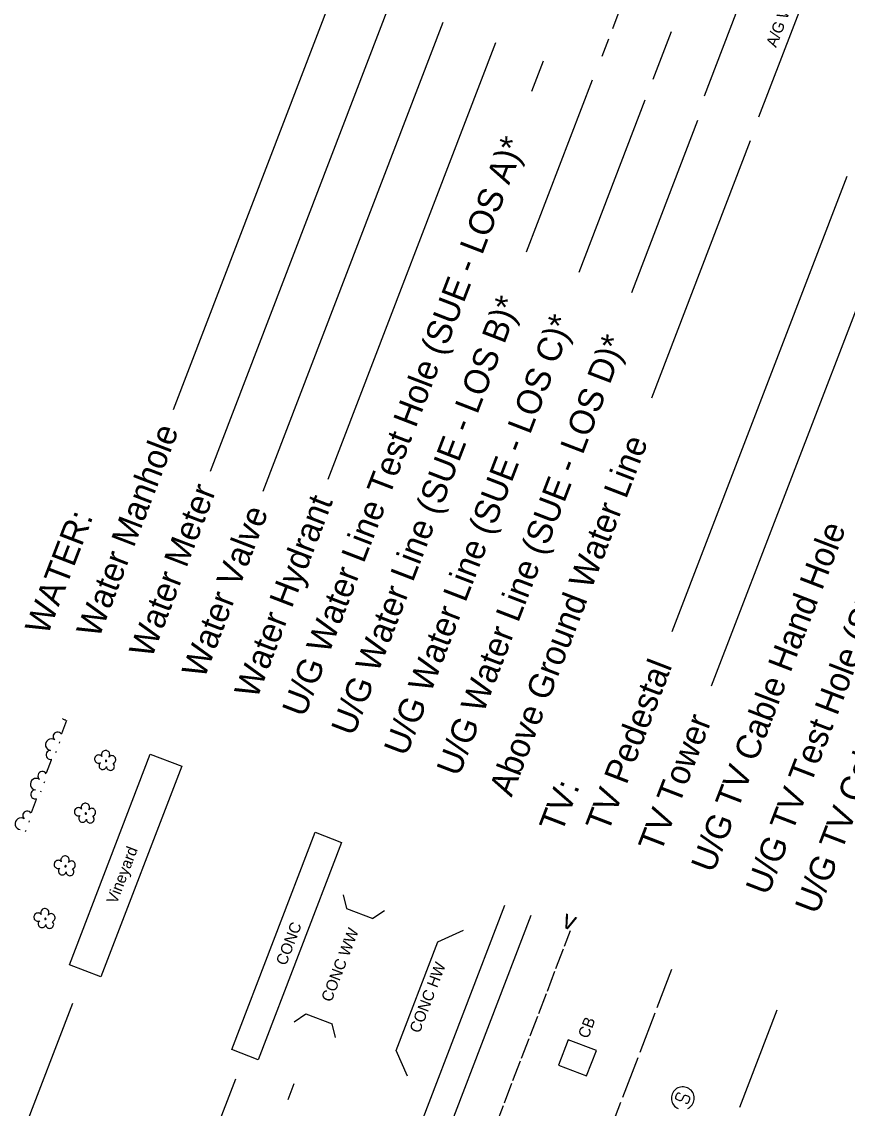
# Model space of a CAD drawing. Extents: x 1015221 to 1064345, y 619216 to 647967.
# Drawn here: x 1047324 to 1049619, y 632823 to 635845 of the extents above; entities that cross this region are included whole.
import ezdxf

# ---------------------------------------------------------------- set-up
doc = ezdxf.new("R2010")
doc.units = 0
doc.layers.add('Default', color=7, linetype='Continuous')

msp = doc.modelspace()

# ---------------------------------------------------------------- linework, layer by layer
at = {"layer": 'Default'}
for p, q in [((1049373.4, 635580.1), (1049609.8, 636195.4)), ((1048201.7, 635954.5), (1047744.7, 634765.2)), ((1049222.1, 635638.2), (1049332.7, 635926.1)), ((1048348.2, 635898.3), (1047847.2, 634594.3)), ((1048967.1, 635825.8), (1048985.4, 635873.4)), ((1048494.7, 635842), (1047993.7, 634538)), ((1049079.3, 635685), (1049130.3, 635817.8)), ((1048641.1, 635785.7), (1048174.6, 634571.4)), ((1048937.6, 635748.9), (1048955.9, 635796.5)), ((1048773.6, 635734.8), (1048741.1, 635650.2)), ((1048910.2, 635682.3), (1048726.2, 635203.5)), ((1049056.7, 635626), (1048872.7, 635147.2)), ((1049203.1, 635569.8), (1049019.2, 635090.9)), ((1049349.6, 635513.5), (1049074.7, 634797.8)), ((1049617.9, 635414.4), (1049131.3, 634148)), ((1049764.4, 635358.2), (1049241.4, 633997)), ((1047434.9, 633865.8), (1047448.9, 633902.4)), ((1047428.5, 633838.4), (1047429.9, 633842)), ((1047418.7, 633812.7), (1047420.1, 633816.4)), ((1047392.6, 633755.9), (1047406.7, 633792.5)), ((1047386.3, 633728.5), (1047387.7, 633732.2)), ((1047376.5, 633702.9), (1047377.9, 633706.5)), ((1047350.4, 633646), (1047364.5, 633682.7)), ((1047344.1, 633618.6), (1047345.5, 633622.3)), ((1047334.3, 633593), (1047335.7, 633596.7)), ((1048217.1, 633417.1), (1048226.5, 633379)), ((1048435, 632784.1), (1048667.1, 633388.3)), ((1048226.5, 633379), (1048299.7, 633350.9)), ((1048332.3, 633372.8), (1048299.7, 633350.9)), ((1048508.2, 632756), (1048740.4, 633360.2)), ((1048480.9, 633286.5), (1048552.6, 633318.4)), ((1048833.3, 633274), (1048850.2, 633318)), ((1048364.8, 632984.4), (1048480.9, 633286.5)), ((1048809.4, 633211.8), (1048830.5, 633266.7)), ((1049090.9, 633103.6), (1049131.7, 633209.8)), ((1048785.5, 633149.5), (1048806.6, 633204.5)), ((1048761.6, 633087.3), (1048782.7, 633142.2)), ((1047465.1, 633114.8), (1046888.4, 631613.8)), ((1048081.4, 633064.1), (1048113.9, 633086)), ((1048113.9, 633086), (1048187.2, 633057.9)), ((1049043.1, 632979.1), (1049085.3, 633089)), ((1049320.7, 632826.5), (1049424.7, 633097.3)), ((1048196.6, 633019.8), (1048187.2, 633057.9)), ((1048737.7, 633025), (1048758.8, 633080)), ((1048713.7, 632962.8), (1048734.9, 633017.7)), ((1048396.7, 632912.7), (1048364.8, 632984.4)), ((1048689.8, 632900.5), (1048710.9, 632955.4)), ((1048995.3, 632854.6), (1049037.5, 632964.5)), ((1047918.1, 632904.5), (1047701.5, 632340.8)), ((1048064.6, 632848.2), (1048081.4, 632892.1)), ((1048665.9, 632838.3), (1048687, 632893.2)), ((1049142.5, 632854.9), (1049145.5, 632862.8)), ((1049153.5, 632844.6), (1049145.7, 632847.6)), ((1049152.6, 632865.7), (1049155.2, 632864.7)), ((1049163.6, 632855.8), (1049160.5, 632848)), ((1049178.6, 632855.8), (1049170.5, 632858.9)), ((1049178.6, 632841), (1049181.6, 632848.9)), ((1048642, 632776), (1048663.1, 632830.9)), ((1048947.4, 632730.1), (1048989.6, 632840)), ((1049169, 632838.7), (1049171.6, 632837.7))]:
    msp.add_line(p, q, dxfattribs=at)
for points in [[(1047577.6, 633781.8), (1047581.9, 633785.2), (1047583.5, 633787.1), (1047584.7, 633789.2), (1047585.2, 633791.5), (1047585.1, 633793.6), (1047584.7, 633795.9), (1047584, 633798.3), (1047582.6, 633800.1), (1047581, 633801.5), (1047579.1, 633803.1), (1047576.8, 633803.5), (1047574.4, 633804), (1047571.7, 633803.4), (1047569.8, 633802.9), (1047568, 633801.5), (1047566, 633799.7), (1047567.2, 633801.7), (1047568.2, 633804.3), (1047568.2, 633806.4), (1047567.9, 633809), (1047567.6, 633811.3), (1047566.3, 633813.5), (1047564.5, 633815.4), (1047562.5, 633816.6), (1047560.4, 633817.8), (1047558.1, 633818.3), (1047555.6, 633818.4), (1047553.2, 633817.6), (1047550.7, 633816.5), (1047548.8, 633815.1), (1047547.3, 633813.2), (1047546.1, 633811.1), (1047545.2, 633808.9), (1047545.1, 633806.5), (1047545.5, 633804.2), (1047546.3, 633801.8)], [(1047456.1, 633222.5), (1047681.2, 633808.4), (1047769.1, 633774.6), (1047543.9, 633188.7), (1047456.1, 633222.5)], [(1047546.3, 633801.8), (1047544.5, 633803.8), (1047542.4, 633805), (1047540.1, 633805.4), (1047537.8, 633805.9), (1047535.5, 633805.5), (1047533.2, 633805.1), (1047531.1, 633803.9), (1047529.3, 633802.5), (1047527.6, 633800.2), (1047526.9, 633798.3), (1047526.4, 633796), (1047526.3, 633793.5), (1047526.7, 633791.3), (1047527.4, 633788.9), (1047529.2, 633786.9), (1047530.7, 633785.5), (1047532.8, 633784.3), (1047535, 633783.4), (1047537.3, 633783), (1047539.6, 633783.4), (1047542.4, 633784), (1047540.6, 633782.6), (1047539.3, 633780.5), (1047538.5, 633778.3), (1047538.5, 633776.2), (1047538.6, 633774.1), (1047539.3, 633771.7), (1047540.2, 633769.7), (1047541.6, 633767.9), (1047543.3, 633766.8), (1047545.7, 633765.5), (1047547.7, 633765.1), (1047549.8, 633765.1), (1047552.2, 633765.9), (1047554.1, 633766.4), (1047555.9, 633767.9), (1047557.9, 633769.6), (1047558.9, 633771.3), (1047559.8, 633773.5), (1047559.8, 633771.4), (1047560.6, 633769), (1047561.6, 633767.3), (1047563.5, 633765.8), (1047565.4, 633764.2), (1047567.3, 633763.5), (1047569.6, 633763), (1047571.9, 633763.4), (1047574.1, 633763.8), (1047576.1, 633764.7), (1047577.9, 633766.1), (1047579.4, 633767.7), (1047580.2, 633769.9), (1047581.1, 633772.1), (1047581.4, 633774), (1047580.6, 633776.4), (1047580.2, 633778.7), (1047577.6, 633781.8)], [(1047556.7, 633790.7), (1047556.3, 633789.6), (1047556.4, 633788.7), (1047556.4, 633787.8), (1047557.5, 633787.4), (1047558.3, 633787.1), (1047559.3, 633787.6), (1047559.7, 633788.7), (1047560, 633789.4), (1047559.5, 633790.4), (1047558.6, 633791.2), (1047557.7, 633791.1), (1047556.7, 633790.7)], [(1047521.4, 633635.3), (1047525.6, 633638.7), (1047527.2, 633640.6), (1047528.4, 633642.7), (1047528.9, 633645), (1047528.9, 633647.1), (1047528.5, 633649.4), (1047527.7, 633651.8), (1047526.3, 633653.6), (1047524.7, 633655), (1047522.8, 633656.6), (1047520.5, 633657.1), (1047518.1, 633657.5), (1047515.4, 633656.9), (1047513.5, 633656.4), (1047511.7, 633655), (1047509.8, 633653.2), (1047511, 633655.3), (1047512, 633657.8), (1047511.9, 633659.9), (1047511.7, 633662.6), (1047511.3, 633664.8), (1047510, 633667), (1047508.2, 633668.9), (1047506.2, 633670.1), (1047504.1, 633671.3), (1047501.8, 633671.8), (1047499.3, 633671.9), (1047496.9, 633671.2), (1047494.4, 633670), (1047492.6, 633668.6), (1047491, 633666.7), (1047489.8, 633664.7), (1047488.9, 633662.5), (1047488.8, 633660), (1047489.2, 633657.7), (1047490, 633655.3)], [(1047490, 633655.3), (1047488.2, 633657.3), (1047486.2, 633658.5), (1047483.8, 633659), (1047481.5, 633659.4), (1047479.2, 633659), (1047477, 633658.7), (1047474.8, 633657.4), (1047473, 633656), (1047471.3, 633653.7), (1047470.6, 633651.9), (1047470.1, 633649.5), (1047470, 633647), (1047470.4, 633644.8), (1047471.1, 633642.4), (1047472.9, 633640.5), (1047474.5, 633639), (1047476.5, 633637.8), (1047478.7, 633637), (1047481.1, 633636.5), (1047483.3, 633636.9), (1047486.1, 633637.5), (1047484.3, 633636.1), (1047483.1, 633634), (1047482.2, 633631.8), (1047482.2, 633629.7), (1047482.3, 633627.6), (1047483, 633625.2), (1047483.9, 633623.2), (1047485.3, 633621.4), (1047487, 633620.3), (1047489.5, 633619), (1047491.4, 633618.6), (1047493.5, 633618.7), (1047495.9, 633619.4), (1047497.8, 633620), (1047499.6, 633621.4), (1047501.6, 633623.1), (1047502.6, 633624.8), (1047503.5, 633627), (1047503.5, 633624.9), (1047504.3, 633622.5), (1047505.3, 633620.9), (1047507.2, 633619.3), (1047509.1, 633617.7), (1047511, 633617), (1047513.3, 633616.5), (1047515.6, 633616.9), (1047517.8, 633617.3), (1047519.9, 633618.2), (1047521.7, 633619.6), (1047523.1, 633621.2), (1047523.9, 633623.4), (1047524.8, 633625.6), (1047525.1, 633627.5), (1047524.4, 633629.9), (1047524, 633632.2), (1047521.4, 633635.3)], [(1047500.4, 633644.2), (1047500, 633643.1), (1047500.1, 633642.2), (1047500.2, 633641.3), (1047501.3, 633640.9), (1047502, 633640.6), (1047503, 633641.1), (1047503.4, 633642.2), (1047503.7, 633642.9), (1047503.3, 633643.9), (1047502.3, 633644.7), (1047501.4, 633644.6), (1047500.4, 633644.2)], [(1047907.7, 632986.7), (1048139.8, 633590.9), (1048213.1, 633562.8), (1047980.9, 632958.5), (1047907.7, 632986.7)], [(1047433.7, 633508.8), (1047431.9, 633510.8), (1047429.9, 633512), (1047427.5, 633512.5), (1047425.2, 633513), (1047422.9, 633512.6), (1047420.7, 633512.2), (1047418.5, 633510.9), (1047416.7, 633509.5), (1047415, 633507.2), (1047414.3, 633505.4), (1047413.8, 633503), (1047413.7, 633500.6), (1047414.1, 633498.3), (1047414.9, 633495.9), (1047416.6, 633494), (1047418.2, 633492.5), (1047420.2, 633491.3), (1047422.4, 633490.5), (1047424.8, 633490), (1047427, 633490.4), (1047429.8, 633491), (1047428, 633489.6), (1047426.8, 633487.6), (1047425.9, 633485.4), (1047426, 633483.2), (1047426, 633481.1), (1047426.8, 633478.7), (1047427.7, 633476.7), (1047429.1, 633474.9), (1047430.8, 633473.8), (1047433.2, 633472.5), (1047435.2, 633472.1), (1047437.3, 633472.2), (1047439.7, 633472.9), (1047441.5, 633473.5), (1047443.3, 633474.9), (1047445.3, 633476.7), (1047446.4, 633478.4), (1047447.2, 633480.5), (1047447.2, 633478.4), (1047448, 633476), (1047449, 633474.4), (1047451, 633472.8), (1047452.9, 633471.2), (1047454.7, 633470.5), (1047457, 633470), (1047459.3, 633470.4), (1047461.5, 633470.8), (1047463.6, 633471.7), (1047465.4, 633473.1), (1047466.8, 633474.7), (1047467.7, 633476.9), (1047468.5, 633479.1), (1047468.8, 633481.1), (1047468.1, 633483.5), (1047467.7, 633485.7), (1047465.1, 633488.8)], [(1047465.1, 633488.8), (1047469.3, 633492.2), (1047470.9, 633494.1), (1047472.1, 633496.2), (1047472.6, 633498.5), (1047472.6, 633500.6), (1047472.2, 633502.9), (1047471.4, 633505.3), (1047470, 633507.1), (1047468.5, 633508.5), (1047466.5, 633510.1), (1047464.2, 633510.6), (1047461.9, 633511.1), (1047459.1, 633510.4), (1047457.2, 633509.9), (1047455.4, 633508.5), (1047453.5, 633506.7), (1047454.7, 633508.8), (1047455.7, 633511.3), (1047455.6, 633513.4), (1047455.4, 633516.1), (1047455, 633518.3), (1047453.7, 633520.5), (1047452, 633522.4), (1047449.9, 633523.6), (1047447.8, 633524.9), (1047445.5, 633525.3), (1047443, 633525.4), (1047440.6, 633524.7), (1047438.1, 633523.6), (1047436.3, 633522.1), (1047434.7, 633520.2), (1047433.5, 633518.2), (1047432.7, 633516), (1047432.5, 633513.5), (1047432.9, 633511.2), (1047433.7, 633508.8)], [(1047444.1, 633497.7), (1047443.7, 633496.6), (1047443.8, 633495.7), (1047443.9, 633494.9), (1047445, 633494.4), (1047445.7, 633494.2), (1047446.7, 633494.6), (1047447.1, 633495.7), (1047447.4, 633496.4), (1047447, 633497.4), (1047446, 633498.2), (1047445.1, 633498.2), (1047444.1, 633497.7)], [(1047377.4, 633362.4), (1047375.6, 633364.3), (1047373.6, 633365.5), (1047371.3, 633366), (1047368.9, 633366.5), (1047366.7, 633366.1), (1047364.4, 633365.7), (1047362.2, 633364.4), (1047360.4, 633363), (1047358.7, 633360.7), (1047358, 633358.9), (1047357.5, 633356.6), (1047357.4, 633354.1), (1047357.8, 633351.8), (1047358.6, 633349.4), (1047360.4, 633347.5), (1047361.9, 633346.1), (1047364, 633344.8), (1047366.2, 633344), (1047368.5, 633343.5), (1047370.8, 633343.9), (1047373.5, 633344.5), (1047371.7, 633343.1), (1047370.5, 633341.1), (1047369.7, 633338.9), (1047369.7, 633336.8), (1047369.7, 633334.6), (1047370.5, 633332.3), (1047371.4, 633330.2), (1047372.8, 633328.4), (1047374.5, 633327.4), (1047376.9, 633326), (1047378.9, 633325.7), (1047381, 633325.7), (1047383.4, 633326.5), (1047385.3, 633327), (1047387.1, 633328.4), (1047389, 633330.2), (1047390.1, 633331.9), (1047390.9, 633334.1), (1047391, 633332), (1047391.7, 633329.6), (1047392.8, 633327.9), (1047394.7, 633326.3), (1047396.6, 633324.7), (1047398.4, 633324), (1047400.8, 633323.6), (1047403, 633324), (1047405.3, 633324.4), (1047407.3, 633325.3), (1047409.1, 633326.7), (1047410.5, 633328.2), (1047411.4, 633330.4), (1047412.2, 633332.6), (1047412.6, 633334.6), (1047411.8, 633337), (1047411.4, 633339.2), (1047408.8, 633342.3)], [(1047408.8, 633342.3), (1047413.1, 633345.7), (1047414.6, 633347.6), (1047415.8, 633349.7), (1047416.3, 633352), (1047416.3, 633354.2), (1047415.9, 633356.4), (1047415.1, 633358.8), (1047413.7, 633360.6), (1047412.2, 633362), (1047410.3, 633363.6), (1047407.9, 633364.1), (1047405.6, 633364.6), (1047402.8, 633364), (1047400.9, 633363.4), (1047399.1, 633362), (1047397.2, 633360.2), (1047398.4, 633362.3), (1047399.4, 633364.9), (1047399.4, 633367), (1047399.1, 633369.6), (1047398.7, 633371.8), (1047397.4, 633374), (1047395.7, 633375.9), (1047393.6, 633377.2), (1047391.6, 633378.4), (1047389.2, 633378.8), (1047386.7, 633379), (1047384.3, 633378.2), (1047381.8, 633377.1), (1047380, 633375.7), (1047378.4, 633373.7), (1047377.2, 633371.7), (1047376.4, 633369.5), (1047376.3, 633367), (1047376.7, 633364.8), (1047377.4, 633362.4)], [(1047387.8, 633351.2), (1047387.4, 633350.1), (1047387.5, 633349.2), (1047387.6, 633348.4), (1047388.7, 633347.9), (1047389.4, 633347.7), (1047390.4, 633348.1), (1047390.9, 633349.2), (1047391.1, 633349.9), (1047390.7, 633351), (1047389.7, 633351.8), (1047388.9, 633351.7), (1047387.8, 633351.2)], [(1049176, 632822.9), (1049179.5, 632824.8), (1049182.6, 632827.2), (1049185.5, 632829.9), (1049188.1, 632833), (1049190.3, 632836.5), (1049191.9, 632840), (1049193.1, 632843.9), (1049193.8, 632847.7), (1049194, 632851.8), (1049193.6, 632855.7), (1049192.8, 632859.6), (1049191.6, 632863.3), (1049189.7, 632867.1), (1049187.7, 632870.3), (1049185.1, 632873.5), (1049182, 632876), (1049178.8, 632878.4), (1049175.4, 632880.2), (1049171.6, 632881.7), (1049167.8, 632882.6), (1049163.7, 632883.1), (1049159.9, 632883.2), (1049155.8, 632882.5), (1049152.1, 632881.5), (1049148.3, 632880), (1049144.8, 632878), (1049141.7, 632875.7), (1049138.8, 632873), (1049136.2, 632869.9), (1049134, 632866.3), (1049132.4, 632862.9)], [(1049132.4, 632862.9), (1049131.2, 632859), (1049130.5, 632855.1), (1049130.4, 632851.1), (1049130.7, 632847.1), (1049131.5, 632843.3), (1049132.7, 632839.5), (1049134.6, 632835.8), (1049136.6, 632832.6), (1049139.2, 632829.4), (1049142.3, 632826.8), (1049145.5, 632824.5), (1049148.9, 632822.7)], [(1049145.7, 632847.6), (1049144.2, 632848.8), (1049143.1, 632850), (1049142.5, 632851.3), (1049142.3, 632853.1), (1049142.5, 632854.9)], [(1049145.5, 632862.8), (1049146.5, 632864), (1049147.8, 632865.1), (1049149.2, 632866), (1049150.9, 632866.1), (1049152.6, 632865.7)], [(1049160.5, 632848), (1049159.7, 632846.4), (1049158.4, 632845.2), (1049156.8, 632844.7), (1049155.1, 632844.6), (1049153.5, 632844.6)], [(1049170.7, 632858.8), (1049169, 632859.2), (1049167.3, 632859), (1049165.6, 632858.3), (1049164.3, 632857.1), (1049163.6, 632855.8)], [(1049181.6, 632848.9), (1049181.9, 632850.4), (1049181.8, 632852.1), (1049181, 632853.7), (1049179.9, 632855), (1049178.3, 632855.9)], [(1049171.4, 632837.8), (1049173.2, 632837.6), (1049174.9, 632837.8), (1049176.5, 632838.3), (1049177.7, 632839.4), (1049178.6, 632841)]]:
    msp.add_lwpolyline(points, dxfattribs=at)
msp.add_lwpolyline([(1048894.6, 632913.8), (1048921.6, 632984.2), (1048843.7, 633014.1), (1048816.6, 632943.7)], close=True, dxfattribs=at)
for centre, radius, start, end in [((1047445.6, 633915.8), 12.4, 225.234, 272.732), ((1047405.9, 633834.4), 16.2, 54.9468, 263.0193), ((1047423.1, 633857.2), 12.4, 29.7515, 230.5481), ((1047403.4, 633806), 12.4, 87.418, 288.2145), ((1047380.8, 633747.4), 12.4, 29.7515, 230.5481), ((1047363.7, 633724.6), 16.2, 54.9468, 263.0193), ((1047361.1, 633696.1), 12.4, 87.418, 288.2145), ((1047321.5, 633614.7), 16.2, 54.9468, 263.0193), ((1047338.6, 633637.5), 12.4, 29.7515, 230.5481)]:
    msp.add_arc(centre, radius, start, end, dxfattribs=at)

# ---------------------------------------------------------------- texts
for s, height, rotation, p in [('A/G Water', 31.38, 68.983, (1049421.6, 635771.1)), ('U/G Water Line Test Hole (SUE - LOS A)*', 68.654, 68.983, (1048109.8, 633907.8)), ('U/G Water Line (SUE - LOS B)*', 68.654, 68.983, (1048246.4, 633855.4)), ('U/G Water Line (SUE - LOS C)*', 68.654, 68.983, (1048392.9, 633799.1)), ('U/G Water Line (SUE - LOS D)*', 68.654, 68.983, (1048539.4, 633742.8)), ('Water Manhole', 68.654, 68.983, (1047537.9, 634127.6)), ('U/G TV Test Hole (SUE - LOS A)*', 68.654, 68.983, (1049399, 633412.5)), ('Above Ground Water Line', 68.654, 68.983, (1048685.8, 633686.5)), ('Water Meter', 68.654, 68.983, (1047684.4, 634071.3)), ('Water Hydrant', 68.654, 68.983, (1047977.3, 633958.7)), ('U/G TV Cable (SUE - LOS B)*', 68.654, 68.983, (1049536.1, 633359.8)), ('WATER:', 68.65, 68.983, (1047395, 634135.6)), ('Water Valve', 68.654, 68.983, (1047830.9, 634015)), ('U/G TV Cable Hand Hole', 68.654, 68.983, (1049247.1, 633474.9)), ('TV Pedestal', 68.654, 68.983, (1048954.1, 633587.5)), ('TV Tower', 68.65, 68.983, (1049100.6, 633531.2)), ('TV:', 68.65, 68.983, (1048825.1, 633586.2)), ('Vineyard', 31.38, 68.983, (1047587.3, 633389.1)), ('v', 51.8, 339.2239, (1048822.8, 633328.4)), ('CONC', 31.38, 68.983, (1048058.5, 633218.2)), ('CONC WW', 31.38, 68.983, (1048184.6, 633116.7)), ('CONC HW', 31.38, 68.983, (1048430, 633030.2)), ('CB', 31.38, 68.983, (1048898.7, 633015.2))]:
    msp.add_text(s, height=height, rotation=rotation, dxfattribs=at).set_placement(p)

doc.saveas('drawing.dxf')
